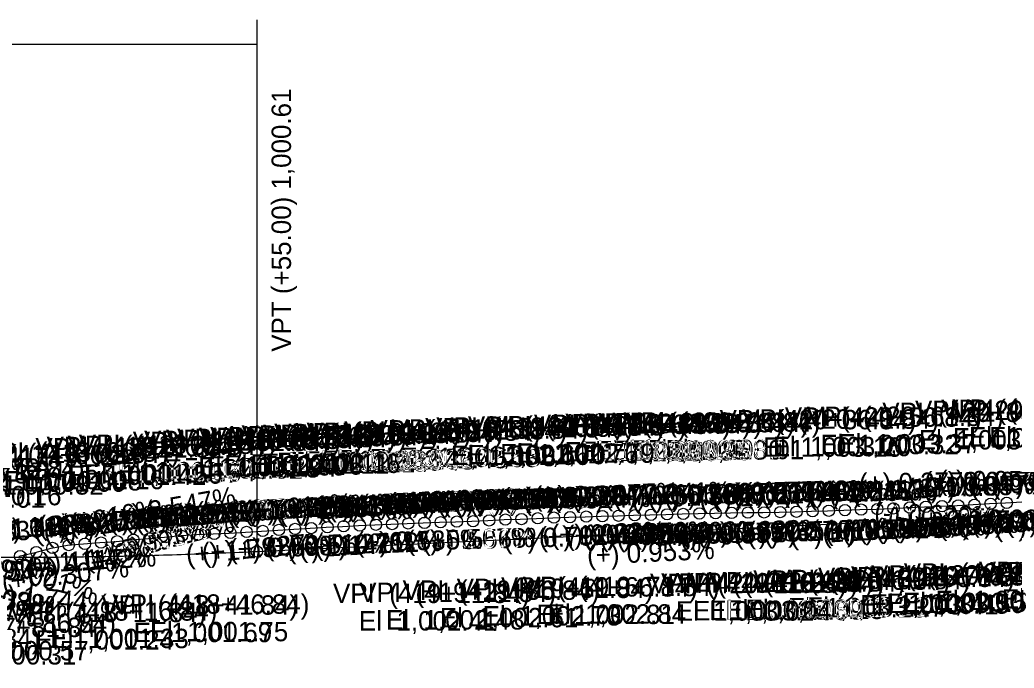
# Model space of a CAD drawing. Extents: x 150 to 16976893, y 3102 to 12559827.
# Drawn here: x 16976174.7 to 16976482, y 12558906.3 to 12559106.8 of the extents above; entities that cross this region are included whole.
import ezdxf

# ---------------------------------------------------------------- set-up
doc = ezdxf.new("R2010")
doc.units = 0
for name, color, linetype in [('RD_DDB_GradeTX', 7, 'Continuous'), ('RD_DDB_PI', 7, 'Continuous'), ('RD_DDB_Profile_EX', 7, 'Continuous'), ('RD_HC_TX_Sta20', 7, 'Continuous'), ('RD_XS_Misc_Line', 7, 'Continuous')]:
    doc.layers.add(name, color=color, linetype=linetype)

msp = doc.modelspace()

# ---------------------------------------------------------------- linework, layer by layer
at = {"layer": 'RD_DDB_PI'}
for centre in [(16976414.74, 12558954.64), (16976419.74, 12558954.78), (16976424.74, 12558954.95), (16976429.74, 12558955.13), (16976434.74, 12558955.3), (16976439.74, 12558955.47), (16976444.74, 12558955.67), (16976449.74, 12558955.93), (16976454.74, 12558956.15), (16976459.74, 12558956.36), (16976464.74, 12558956.58), (16976469.74, 12558956.79), (16976474.74, 12558957.09), (16976479.74, 12558957.39), (16976309.74, 12558951.58), (16976314.74, 12558951.7), (16976319.74, 12558951.96), (16976324.74, 12558952.21), (16976329.74, 12558952.38), (16976334.74, 12558952.6), (16976339.74, 12558952.81), (16976344.74, 12558952.94), (16976349.74, 12558953.11), (16976354.74, 12558953.26), (16976359.74, 12558953.39), (16976364.74, 12558953.53), (16976369.74, 12558953.68), (16976374.74, 12558953.83), (16976379.74, 12558953.96), (16976384.74, 12558954.1), (16976389.74, 12558954.2), (16976394.74, 12558954.3), (16976399.74, 12558954.37), (16976404.74, 12558954.44), (16976409.74, 12558954.53), (16976249.74, 12558948.71), (16976254.74, 12558949.02), (16976259.74, 12558949.32), (16976264.74, 12558949.59), (16976269.74, 12558949.87), (16976274.74, 12558950.12), (16976279.74, 12558950.37), (16976284.74, 12558950.61), (16976289.74, 12558950.83), (16976294.74, 12558951.03), (16976299.74, 12558951.2), (16976304.74, 12558951.38), (16976204.74, 12558945.49), (16976209.74, 12558945.94), (16976214.74, 12558946.4), (16976219.74, 12558946.8), (16976224.74, 12558947.16), (16976229.74, 12558947.51), (16976234.74, 12558947.79), (16976239.74, 12558948.07), (16976244.74, 12558948.39), (16976184.74, 12558943.43), (16976189.74, 12558944.31), (16976194.74, 12558944.71), (16976199.74, 12558945.1), (16976174.74, 12558940.88), (16976179.74, 12558942.15)]:
    msp.add_circle(centre, 1.75, dxfattribs=at)
at = {"layer": 'RD_DDB_Profile_EX'}
for points in [[(16976259.37, 12558949.28), (16976264.37, 12558949.56), (16976269.37, 12558949.85), (16976274.37, 12558950.11), (16976279.37, 12558950.36), (16976284.37, 12558950.6), (16976289.37, 12558950.83), (16976294.37, 12558951.03), (16976299.37, 12558951.2), (16976304.37, 12558951.36), (16976309.37, 12558951.55), (16976314.37, 12558951.69), (16976319.37, 12558951.96), (16976324.37, 12558952.22), (16976329.37, 12558952.37), (16976334.37, 12558952.57), (16976339.37, 12558952.77), (16976344.37, 12558952.91), (16976349.37, 12558953.09), (16976354.37, 12558953.25), (16976359.37, 12558953.39), (16976364.37, 12558953.53), (16976369.37, 12558953.68), (16976374.37, 12558953.82), (16976379.37, 12558953.96), (16976384.37, 12558954.09), (16976389.37, 12558954.19), (16976394.37, 12558954.28), (16976399.37, 12558954.35), (16976404.37, 12558954.41), (16976409.37, 12558954.51), (16976414.37, 12558954.62), (16976419.37, 12558954.76), (16976424.37, 12558954.93), (16976429.37, 12558955.11), (16976434.37, 12558955.29), (16976439.37, 12558955.46), (16976444.37, 12558955.67), (16976449.37, 12558955.92), (16976454.37, 12558956.13), (16976459.37, 12558956.34), (16976464.37, 12558956.59), (16976469.37, 12558956.88), (16976474.37, 12558957.17), (16976479.37, 12558957.41), (16976484.37, 12558957.67)], [(16976174.37, 12558940.84), (16976179.37, 12558942.07), (16976184.37, 12558943.34), (16976189.37, 12558944.29), (16976194.37, 12558944.68), (16976199.37, 12558945.08), (16976204.37, 12558945.47), (16976209.37, 12558945.92), (16976214.37, 12558946.38), (16976219.37, 12558946.79), (16976224.37, 12558947.26), (16976229.37, 12558947.6), (16976234.37, 12558947.81), (16976239.37, 12558948.04), (16976244.37, 12558948.35), (16976249.37, 12558948.67), (16976254.37, 12558948.98), (16976259.37, 12558949.28)]]:
    msp.add_lwpolyline(points, dxfattribs=at)
at = {"layer": 'RD_HC_TX_Sta20'}
for p, q in [((16976247.9, 12559106.77), (16976247.9, 12558944.11)), ((16975697.9, 12559099.27), (16976247.9, 12559099.27))]:
    msp.add_line(p, q, dxfattribs=at)
msp.add_circle((16976247.9, 12558942.36), 1.75, dxfattribs=at)
at = {"layer": 'RD_XS_Misc_Line'}
msp.add_line((16976247.9, 12558942.36), (16976567.9, 12558957.61), dxfattribs=at)
msp.add_spline([(16975697.9, 12559011.77), (16975708.9, 12559008.5), (16975719.9, 12559005.32), (16975730.9, 12559002.21), (16975741.9, 12558999.18), (16975752.9, 12558996.22), (16975763.9, 12558993.34), (16975774.9, 12558990.54), (16975785.9, 12558987.81), (16975796.9, 12558985.16), (16975807.9, 12558982.59), (16975818.9, 12558980.09), (16975829.9, 12558977.67), (16975840.9, 12558975.33), (16975851.9, 12558973.06), (16975862.9, 12558970.87), (16975873.9, 12558968.76), (16975884.9, 12558966.72), (16975895.9, 12558964.76), (16975906.9, 12558962.87), (16975917.9, 12558961.06), (16975928.9, 12558959.33), (16975939.9, 12558957.67), (16975950.9, 12558956.09), (16975961.9, 12558954.59), (16975972.9, 12558953.17), (16975983.9, 12558951.82), (16975994.9, 12558950.54), (16976005.9, 12558949.35), (16976016.9, 12558948.23), (16976027.9, 12558947.18), (16976038.9, 12558946.21), (16976049.9, 12558945.32), (16976060.9, 12558944.51), (16976071.9, 12558943.77), (16976082.9, 12558943.11), (16976093.9, 12558942.52), (16976104.9, 12558942.02), (16976115.9, 12558941.58), (16976126.9, 12558941.23), (16976137.9, 12558940.95), (16976148.9, 12558940.75), (16976159.9, 12558940.62), (16976170.9, 12558940.57), (16976181.9, 12558940.6), (16976192.9, 12558940.7), (16976203.9, 12558940.88), (16976214.9, 12558941.14), (16976225.9, 12558941.47), (16976236.9, 12558941.88), (16976247.9, 12558942.36)], degree=3, dxfattribs=at)

# ---------------------------------------------------------------- texts
at = {"layer": 'RD_DDB_GradeTX'}
for s, rotation, p in [('(+) 1.124%', 3.2161, (16976431.86, 12558957.76)), ('(+) 0.277%', 0.7937, (16976434.06, 12558960.44)), ('(+) 0.684%', 1.9574, (16976448.86, 12558958.79)), ('(+) 0.657%', 1.8825, (16976453.92, 12558958.93)), ('(+) 0.067%', 0.1931, (16976454.14, 12558960.91)), ('(-) 0.056%', 359.8391, (16976458.75, 12558961.3)), ('(+) 0.863%', 2.4706, (16976468.41, 12558959.74)), ('(+) 0.851%', 2.4373, (16976475.13, 12558960.02)), ('(+) 0.400%', 1.1454, (16976323.81, 12558955.88)), ('(+) 0.391%', 1.1187, (16976330.17, 12558956.04)), ('(+) 0.284%', 0.8126, (16976333.58, 12558956.43)), ('(+) 0.977%', 2.7964, (16976339.28, 12558955.92)), ('(+) 0.712%', 2.038, (16976345.33, 12558955.94)), ('(+) 0.841%', 2.4083, (16976355.36, 12558956.47)), ('(+) 0.535%', 1.5325, (16976358.12, 12558956.3)), ('(+) 0.736%', 2.1075, (16976363.79, 12558955.71)), ('(+) 0.586%', 1.6795, (16976368.64, 12558956.67)), ('(+) 0.684%', 1.9574, (16976368.91, 12558956.05)), ('(+) 0.507%', 1.4514, (16976373.83, 12558956.74)), ('(+) 1.022%', 2.9245, (16976384.85, 12558955.62)), ('(+) 0.863%', 2.4706, (16976388.49, 12558956.29)), ('(+) 0.572%', 1.6372, (16976388.58, 12558957.22)), ('(+) 0.551%', 1.5767, (16976395.06, 12558957.39)), ('(+) 0.548%', 1.5691, (16976398.65, 12558957.48)), ('(+) 0.400%', 1.1454, (16976403.79, 12558957.48)), ('(+) 0.391%', 1.1187, (16976410.15, 12558957.6)), ('(+) 0.284%', 0.8126, (16976413.57, 12558957.57)), ('(+) 1.211%', 3.465, (16976418.39, 12558956.69)), ('(+) 0.268%', 0.7673, (16976418.58, 12558957.62)), ('(+) 1.242%', 3.5532, (16976424.98, 12558956.99)), ('(+) 3.547%', 10.0575, (16976202.92, 12558949.7)), ('(+) 1.611%', 4.6059, (16976238.5, 12558951.32)), ('(+) 1.432%', 4.0959, (16976239.71, 12558951.24)), ('(+) 0.792%', 2.2674, (16976243.85, 12558951.97)), ('(+) 1.398%', 3.9989, (16976244.95, 12558951.58)), ('(+) 1.117%', 3.1973, (16976253.79, 12558951.85)), ('(+) 1.033%', 2.9562, (16976254.73, 12558951.61)), ('(+) 0.977%', 2.7964, (16976259.38, 12558952.02)), ('(+) 1.271%', 3.6374, (16976266.87, 12558952.8)), ('(+) 0.850%', 2.4346, (16976268.55, 12558952.79)), ('(+) 1.245%', 3.5625, (16976269.93, 12558952.97)), ('(+) 0.841%', 2.4083, (16976275.44, 12558953.11)), ('(+) 1.191%', 3.407, (16976278.6, 12558953.45)), ('(+) 1.104%', 3.1607, (16976281.96, 12558953.55)), ('(+) 0.690%', 1.9757, (16976283.91, 12558953.84)), ('(+) 1.100%', 3.147, (16976286.85, 12558953.81)), ('(+) 0.586%', 1.6795, (16976288.68, 12558954.32)), ('(+) 1.015%', 2.9063, (16976291.75, 12558953.99)), ('(+) 0.983%', 2.8136, (16976293.39, 12558954.04)), ('(+) 0.953%', 2.7275, (16976298.28, 12558954.25)), ('(+) 0.620%', 1.7751, (16976303.56, 12558954.63)), ('(+) 0.915%', 2.619, (16976305.23, 12558954.55)), ('(+) 0.572%', 1.6372, (16976308.62, 12558954.94)), ('(+) 0.768%', 2.1989, (16976309.02, 12558954.58)), ('(+) 0.703%', 2.0127, (16976313.62, 12558954.69)), ('(+) 0.551%', 1.5767, (16976315.1, 12558955.19)), ('(+) 0.548%', 1.5691, (16976318.68, 12558955.29)), ('(+) 0.698%', 1.9992, (16976318.86, 12558954.87)), ('(+) 0.514%', 1.4734, (16976330.31, 12558955.11)), ('(+) 3.916%', 11.0782, (16976179.37, 12558945.29)), ('(+) 3.025%', 8.6021, (16976182.43, 12558945.08)), ('(+) 2.990%', 8.5027, (16976188.09, 12558945.9)), ('(+) 1.245%', 3.5625, (16976190.09, 12558948)), ('(+) 1.191%', 3.407, (16976198.75, 12558948.69)), ('(+) 1.104%', 3.1607, (16976202.09, 12558949.14)), ('(+) 1.100%', 3.147, (16976206.97, 12558949.42)), ('(+) 1.574%', 4.4998, (16976210.39, 12558948.95)), ('(+) 1.015%', 2.9063, (16976211.86, 12558949.93)), ('(+) 0.983%', 2.8136, (16976213.49, 12558950.12)), ('(+) 1.566%', 4.4779, (16976215.21, 12558949.32)), ('(+) 0.953%', 2.7275, (16976218.37, 12558950.45)), ('(+) 1.559%', 4.4561, (16976219.98, 12558949.69)), ('(+) 0.915%', 2.619, (16976225.32, 12558950.89)), ('(+) 0.768%', 2.1989, (16976229.08, 12558951.51)), ('(+) 0.703%', 2.0127, (16976233.67, 12558951.88)), ('(-) 0.690%', 358.0253, (16976438.7, 12558951.45)), ('(-) 0.325%', 359.0691, (16976442.95, 12558950.19)), ('(+) 1.611%', 4.6059, (16976158.77, 12558944.9)), ('(+) 1.432%', 4.0959, (16976159.93, 12558945.52)), ('(+) 1.398%', 3.9989, (16976165.16, 12558946)), ('(+) 1.276%', 3.6497, (16976180.51, 12558947.3)), ('(+) 1.271%', 3.6374, (16976187.04, 12558947.73)), ('(+) 5.113%', 14.3396, (16976203.18, 12558938.85)), ('(+) 1.196%', 3.4227, (16976422.93, 12558944.98)), ('(+) 0.580%', 1.6604, (16976433.87, 12558946.19)), ('(+) 0.665%', 1.9052, (16976439.14, 12558946.42)), ('(+) 0.736%', 2.1075, (16976444.17, 12558946.66)), ('(+) 0.045%', 0.1295, (16976448.76, 12558948.96)), ('(+) 0.835%', 2.3896, (16976458.68, 12558947.25)), ('(-) 0.088%', 359.7485, (16976463.7, 12558949.38)), ('(+) 1.022%', 2.9245, (16976465.35, 12558947.72)), ('(+) 0.248%', 0.709, (16976468.74, 12558948.34)), ('(+) 0.751%', 2.1499, (16976475.95, 12558946.94)), ('(+) 0.870%', 2.4914, (16976479.41, 12558948.21)), ('(+) 1.837%', 5.2476, (16976150.39, 12558943.5)), ('(+) 5.093%', 14.2874, (16976195.08, 12558936.77)), ('(+) 0.792%', 2.2674, (16976324.26, 12558943.14)), ('(+) 1.033%', 2.9562, (16976335.24, 12558943.75)), ('(+) 0.268%', 0.7673, (16976338.75, 12558944.55)), ('(+) 0.392%', 1.1218, (16976343.51, 12558944.24)), ('(+) 0.403%', 1.1545, (16976348.75, 12558944.3)), ('(+) 0.850%', 2.4346, (16976348.98, 12558944.19)), ('(+) 0.580%', 1.6604, (16976353.91, 12558943.87)), ('(+) 0.665%', 1.9052, (16976359.19, 12558943.76)), ('(+) 0.690%', 1.9757, (16976364.27, 12558944.61)), ('(+) 0.657%', 1.8825, (16976374.36, 12558944.31)), ('(+) 0.835%', 2.3896, (16976378.76, 12558943.91)), ('(+) 0.568%', 1.626, (16976378.99, 12558944.93)), ('(+) 0.620%', 1.7751, (16976383.89, 12558945.12)), ('(+) 0.851%', 2.4373, (16976395.71, 12558944.62)), ('(+) 0.870%', 2.4914, (16976399.49, 12558944.73)), ('(+) 0.877%', 2.51, (16976404.78, 12558944.94)), ('(+) 1.189%', 3.4011, (16976412.81, 12558944.4)), ('(+) 0.392%', 1.1218, (16976423.5, 12558945.8)), ('(+) 0.403%', 1.1545, (16976428.74, 12558945.92)), ('(+) 1.792%', 5.1194, (16976226.29, 12558938.38)), ('(+) 1.837%', 5.2476, (16976231.13, 12558938.86)), ('(+) 0.698%', 1.9992, (16976239.33, 12558940.09)), ('(+) 0.514%', 1.4734, (16976250.64, 12558941.05)), ('(+) 1.142%', 3.2679, (16976257.4, 12558940.07)), ('(+) 1.276%', 3.6497, (16976261.1, 12558940.42)), ('(+) 0.712%', 2.038, (16976265.81, 12558941.1)), ('(+) 0.535%', 1.5325, (16976278.47, 12558942.16)), ('(+) 0.507%', 1.4514, (16976294.16, 12558942.72)), ('(+) 0.568%', 1.626, (16976299.02, 12558942.66)), ('(+) 4.146%', 11.7127, (16976177.13, 12558932.81)), ('(+) 0.953%', 2.7269, (16976350.13, 12558938.18)), ('(-) 5.001%', 345.9615, (16976160.39, 12558936.4)), ('(+) 1.117%', 3.1973, (16976174.59, 12558935.41)), ('(+) 1.142%', 3.2679, (16976177.54, 12558935.51)), ('(+) 1.559%', 4.4561, (16976141.17, 12558931.51)), ('(+) 1.792%', 5.1194, (16976146.63, 12558931.25)), ('(+) 2.307%', 6.5804, (16976169.41, 12558929.99)), ('(-) 4.814%', 346.467, (16976142.94, 12558927.59)), ('(-) 3.133%', 351.0961, (16976147.87, 12558928.07)), ('(-) 3.088%', 351.2241, (16976151.85, 12558927.49)), ('(-) 1.744%', 355.0162, (16976165.06, 12558926.41))]:
    msp.add_text(s, height=6, rotation=rotation, dxfattribs=at).set_placement(p)
at = {"layer": 'RD_DDB_PI'}
for s, p in [('VPI  (420+56.84)', (16976411.15, 12558980.93)), ('VPI  (420+61.84)', (16976417.92, 12558981.15)), ('VPI  (420+86.84)', (16976441.27, 12558982.39)), ('VPI  (420+96.84)', (16976451.39, 12558983)), ('VPI  (421+01.84)', (16976459.46, 12558983.29)), ('VPI  (421+06.84)', (16976462.92, 12558983.35)), ('VPI  (419+46.84)', (16976303.39, 12558977.81)), ('VPI  (419+56.84)', (16976313.16, 12558978.11)), ('VPI  (419+61.84)', (16976319.93, 12558978.26)), ('VPI  (419+76.84)', (16976333.57, 12558978.68)), ('VPI  (419+81.84)', (16976339.81, 12558978.83)), ('VPI  (419+86.84)', (16976343.27, 12558978.96)), ('VPI  (419+91.84)', (16976349.93, 12558979.1)), ('VPI  (419+96.84)', (16976353.39, 12558979.2)), ('VPI  (420+01.84)', (16976357.8, 12558979.3)), ('VPI  (420+06.84)', (16976361.27, 12558979.37)), ('VPI  (420+36.84)', (16976390.97, 12558980.13)), ('VPI  (420+41.84)', (16976397.92, 12558980.3)), ('VPI  (418+71.84)', (16976229.99, 12558974.59)), ('VPI  (418+76.84)', (16976233.45, 12558974.87)), ('VPI  (418+81.84)', (16976239.69, 12558975.12)), ('VPI  (418+86.84)', (16976243.16, 12558975.37)), ('VPI  (418+91.84)', (16976249.81, 12558975.61)), ('VPI  (418+96.84)', (16976253.27, 12558975.83)), ('VPI  (419+01.84)', (16976259.81, 12558976.03)), ('VPI  (419+06.84)', (16976263.27, 12558976.2)), ('VPI  (419+16.84)', (16976274.93, 12558976.58)), ('VPI  (419+26.84)', (16976283.04, 12558976.96)), ('VPI  (419+31.84)', (16976289.51, 12558977.21)), ('VPI  (419+41.84)', (16976299.93, 12558977.6)), ('El  1,003.79', (16976468.05, 12558974.79)), ('El  1,003.81', (16976474.29, 12558974.85)), ('VPI  (418+26.84)', (16976182.92, 12558971.8)), ('VPI  (418+31.84)', (16976189.4, 12558972.16)), ('VPI  (418+36.84)', (16976192.86, 12558972.51)), ('VPI  (418+51.84)', (16976209.57, 12558973.39)), ('VPI  (418+56.84)', (16976213.04, 12558973.71)), ('VPI  (418+61.84)', (16976219.81, 12558974.02)), ('VPI  (418+66.84)', (16976223.27, 12558974.32)), ('El  1,003.16', (16976404.41, 12558971.63)), ('El  1,003.20', (16976407.4, 12558971.8)), ('El  1,003.32', (16976422.13, 12558972.43)), ('El  1,003.37', (16976427.64, 12558972.65)), ('El  1,003.62', (16976452.55, 12558973.89)), ('El  1,003.74', (16976463.05, 12558974.5)), ('VPI  (417+91.84)', (16976150.11, 12558968.43)), ('VPI  (417+96.84)', (16976153.57, 12558969.31)), ('VPI  (418+01.84)', (16976159.69, 12558969.71)), ('VPI  (418+06.84)', (16976163.16, 12558970.1)), ('VPI  (418+21.84)', (16976179.46, 12558971.4)), ('El  1,002.53', (16976292.31, 12558968.46)), ('El  1,002.58', (16976297.61, 12558968.71)), ('El  1,002.66', (16976307.93, 12558969.1)), ('El  1,002.70', (16976312.99, 12558969.31)), ('El  1,002.76', (16976323.11, 12558969.61)), ('El  1,002.79', (16976328.11, 12558969.76)), ('El  1,002.87', (16976342.99, 12558970.18)), ('El  1,002.90', (16976347.81, 12558970.33)), ('El  1,002.93', (16976352.55, 12558970.46)), ('El  1,002.96', (16976357.93, 12558970.6)), ('El  1,002.98', (16976362.84, 12558970.7)), ('El  1,003.00', (16976367.64, 12558970.8)), ('El  1,003.01', (16976374.29, 12558970.87)), ('El  1,001.94', (16976229.82, 12558965.52)), ('El  1,002.00', (16976232.69, 12558965.82)), ('El  1,002.06', (16976237.81, 12558966.09)), ('El  1,002.11', (16976246, 12558966.37)), ('El  1,002.16', (16976249.47, 12558966.62)), ('El  1,002.21', (16976254.11, 12558966.87)), ('El  1,002.26', (16976257.58, 12558967.11)), ('El  1,002.30', (16976262.4, 12558967.33)), ('El  1,002.34', (16976267.52, 12558967.53)), ('El  1,002.38', (16976272.43, 12558967.7)), ('El  1,002.45', (16976282.72, 12558968.08)), ('VPI  (417+66.84)', (16976123.57, 12558963.39)), ('VPI  (417+71.84)', (16976130.28, 12558964.37)), ('VPI  (417+76.84)', (16976133.75, 12558965.13)), ('El  1,001.42', (16976189.5, 12558962.9)), ('El  1,001.50', (16976194.47, 12558963.3)), ('El  1,001.57', (16976199.76, 12558963.66)), ('El  1,001.64', (16976204.82, 12558964.01)), ('El  1,001.82', (16976219.38, 12558964.89)), ('El  1,001.88', (16976224.61, 12558965.21)), ('El  1,000.82', (16976157.72, 12558959.93)), ('El  1,001.00', (16976164.58, 12558960.81)), ('El  1,001.08', (16976169.61, 12558961.21)), ('El  1,001.16', (16976176.36, 12558961.6)), ('El  1,000.16', (16976144.7, 12558956.63)), ('El  1,000.01', (16976139.58, 12558955.87)), ('VPI  (420+71.84)', (16976428.1, 12558931.58)), ('VPI  (420+76.84)', (16976431.56, 12558931.79)), ('VPI  (420+81.84)', (16976437.8, 12558932.09)), ('VPI  (420+91.84)', (16976447.92, 12558932.69)), ('VPI  (421+11.84)', (16976471.11, 12558933.18)), ('VPI  (421+16.84)', (16976474.57, 12558933.1)), ('VPI  (421+21.84)', (16976479.22, 12558933.11)), ('VPI  (419+71.84)', (16976330.11, 12558928.53)), ('VPI  (420+11.84)', (16976369.46, 12558929.44)), ('VPI  (420+16.84)', (16976372.92, 12558929.53)), ('VPI  (420+21.84)', (16976377.57, 12558929.64)), ('VPI  (420+26.84)', (16976381.03, 12558929.78)), ('VPI  (420+31.84)', (16976387.51, 12558929.95)), ('VPI  (420+46.84)', (16976401.39, 12558930.47)), ('VPI  (420+51.84)', (16976407.68, 12558930.67)), ('VPI  (420+66.84)', (16976421.39, 12558931.36)), ('VPI  (419+11.84)', (16976271.46, 12558926.38)), ('VPI  (419+21.84)', (16976279.57, 12558926.7)), ('VPI  (419+36.84)', (16976292.98, 12558927.38)), ('VPI  (419+51.84)', (16976309.69, 12558927.94)), ('VPI  (419+66.84)', (16976323.39, 12558928.39)), ('VPI  (418+41.84)', (16976199.81, 12558922.79)), ('VPI  (418+46.84)', (16976203.27, 12558923.07)), ('El  1,003.41', (16976434.41, 12558922.86)), ('El  1,003.45', (16976437.66, 12558923.08)), ('El  1,003.50', (16976442.52, 12558923.29)), ('El  1,003.56', (16976447.64, 12558923.59)), ('El  1,003.68', (16976457.78, 12558924.19)), ('El  1,003.77', (16976478.23, 12558924.68)), ('VPI  (418+11.84)', (16976171.35, 12558920.49)), ('VPI  (418+16.84)', (16976174.81, 12558920.94)), ('El  1,002.73', (16976317.72, 12558919.44)), ('El  1,002.81', (16976334.35, 12558919.89)), ('El  1,002.84', (16976337.81, 12558920.03)), ('El  1,003.02', (16976377.43, 12558920.94)), ('El  1,003.04', (16976382.75, 12558921.03)), ('El  1,003.06', (16976387.75, 12558921.14)), ('El  1,003.09', (16976392.75, 12558921.28)), ('El  1,003.13', (16976399.02, 12558921.45)), ('El  1,003.23', (16976412.13, 12558921.97)), ('El  1,003.27', (16976417.69, 12558922.17)), ('VPI  (417+86.84)', (16976143.45, 12558917.15)), ('El  1,002.41', (16976279.47, 12558917.88)), ('El  1,002.48', (16976287.84, 12558918.2)), ('El  1,002.61', (16976304.47, 12558918.88)), ('VPI  (417+81.84)', (16976139.99, 12558915.88)), ('El  1,001.69', (16976209.82, 12558914.29)), ('El  1,001.75', (16976214.79, 12558914.57)), ('VPI  (417+61.84)', (16976120.11, 12558912.36)), ('El  1,001.24', (16976179.47, 12558911.99)), ('El  1,001.33', (16976184.02, 12558912.44)), ('El  1,000.31', (16976149.29, 12558907.38)), ('El  1,000.57', (16976153.11, 12558908.65))]:
    msp.add_text(s, height=6, dxfattribs=at).set_placement(p)
at = {"layer": 'RD_HC_TX_Sta20'}
msp.add_text('VPT (+55.00) 1,000.61', height=6, rotation=90, dxfattribs=at).set_placement((16976258.47, 12559004.12))

doc.saveas('drawing.dxf')
